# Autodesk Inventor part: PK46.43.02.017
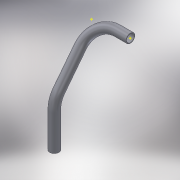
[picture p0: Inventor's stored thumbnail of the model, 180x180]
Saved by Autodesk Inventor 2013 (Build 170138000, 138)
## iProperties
Shininess: 64.0
Length Units: 11269
Angle Units: 11279
Time Units: 11290
Mass Units: 11283
Length Display Precision: 3
Angle Display Precision: 2
Compacted: True
Part Number: PK46.43.02.017
Document SubType Name: Modeling
Created: 2004-12
Material: Сталь высокопрочная низколегированная
Designer: ELarisa
Manufacturer: Standard
Standards Organization: Custom
Density: 7.84 g/cm^3
Density: 0.0
Volumn: 0.0
Area: 0.0
PropertySet Name: Model Information
Control State: 0
Master: False
Checked Out: False
Checked Out Date: 2008-10-09
Last Check In Date: 2008-10-09
Author: ELarisa
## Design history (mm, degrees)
node "РабПлоскость1"
sketch "Эскиз5"
  geometry: C1 r 13 at (0, 0); C2 r 16 at (0, 0)
  constraints: 2 centre point, 1 coincident
  dimensions: "d12" = 32 diameter of C2; "d13" = 26 diameter of C1
sketch "Эскиз6"
  geometry: L1 (16, 0)-(-16, 0) reference; 3 further points
  dimensions: "d14" = 150 distance of point (0, 150) point (0, 0); "d15" = 330 vertical distance of point (130, 330) point (0, 0); "d16" = 130 horizontal distance of point (130, 330) point (0, 0)
node "РабТочка4"
node "РабТочка5"
node "РабТочка7"
node "РабТочка8"
sketch "3М эскиз3" dims "d25" = 80 (= d24)
  geometry: L1 through (80, 122.551) direction (-1, 0); 8 other entities
  constraints: 2 horizontal
  dimensions: "d24" = 80 dimension on L1
feature "Сдвиг3" sketch "3М эскиз3" dims "d26" = 0
body "Solid1"
sketch "Эскиз7"
  geometry: 2 further points
  dimensions: "d22" = 125 distance of point (-125, 330) point (0, 330); "d23" = 0 vertical distance of point (-125, 330) point (0, 330)
